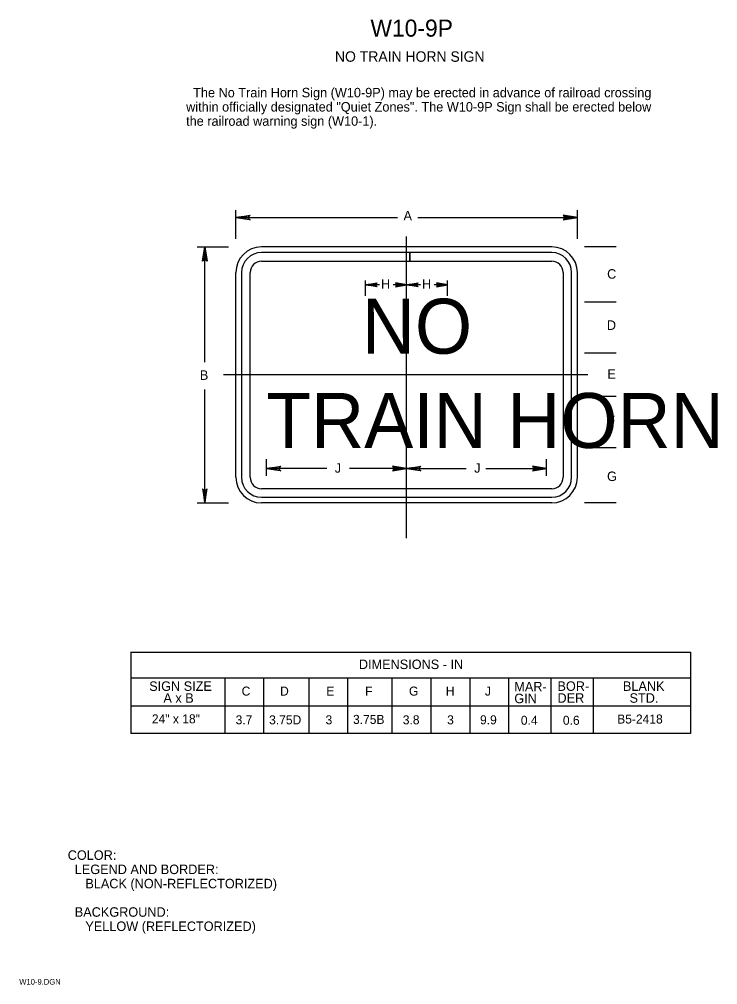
# Model space of a CAD drawing. Extents: x 0.012 to 0.196, y 0.005 to 0.259.
import ezdxf

# ---------------------------------------------------------------- set-up
doc = ezdxf.new("R2010")
doc.units = 0
for name, color, linetype in [('1', 7, 'Continuous'), ('2', 7, 'Continuous'), ('3', 7, 'Continuous')]:
    doc.layers.add(name, color=color, linetype=linetype)

# ---------------------------------------------------------------- blocks, each defined once
blk = doc.blocks.new('RARROW')
at = {"layer": '3'}
for p, q in [((-2.156, 0.285), (-2.2665, 0.384625)), ((-2.2665, 0.384625), (0, 0)), ((0, 0), (-2.2665, -0.379125)), ((-2.156, 0.285), (-2.075625, 0.12075)), ((0, 0), (-2.156, 0.285)), ((-2.14975, -0.2705), (0, 0)), ((-2.075625, 0.12075), (0, 0)), ((0, 0), (-2.074, -0.108)), ((-2.2665, -0.379125), (-2.14975, -0.2705)), ((-2.074, -0.108), (-2.14975, -0.2705))]:
    blk.add_line(p, q, dxfattribs=at)

msp = doc.modelspace()

# ---------------------------------------------------------------- linework, layer by layer
at = {"layer": '1'}
for p, q in [((0.06945, 0.20131), (0.06945, 0.20885)), ((0.15945, 0.20131), (0.15945, 0.20885)), ((0.11445, 0.12237), (0.11445, 0.20194)), ((0.06129, 0.16883), (0.06129, 0.19919)), ((0.11534, 0.19769), (0.0762, 0.19769)), ((0.11534, 0.19769), (0.11534, 0.19544)), ((0.11534, 0.19544), (0.11534, 0.19769)), ((0.1527, 0.19769), (0.11534, 0.19769)), ((0.0762, 0.19544), (0.11534, 0.19544)), ((0.11534, 0.19544), (0.1527, 0.19544)), ((0.07095, 0.19244), (0.07095, 0.13844)), ((0.0732, 0.13844), (0.0732, 0.19244)), ((0.1557, 0.19244), (0.1557, 0.13844)), ((0.15795, 0.13844), (0.15795, 0.19244)), ((0.10365, 0.18625), (0.10365, 0.19033)), ((0.12525, 0.18625), (0.12525, 0.19033)), ((0.16222, 0.16544), (0.06618, 0.16544)), ((0.06129, 0.13169), (0.06129, 0.16162)), ((0.07755, 0.13886), (0.07755, 0.14326)), ((0.15135, 0.13886), (0.15135, 0.14326)), ((0.1527, 0.13544), (0.0762, 0.13544)), ((0.0762, 0.13319), (0.1527, 0.13319))]:
    msp.add_line(p, q, dxfattribs=at)
for centre, radius, start, end in [((0.0762, 0.19244), 0.00675, 90, 180), ((0.1527, 0.19244), 0.00675, 360, 90), ((0.0762, 0.19244), 0.00525, 90, 180), ((0.1527, 0.19244), 0.00525, 0, 90), ((0.0762, 0.19244), 0.003, 90, 180), ((0.1527, 0.19244), 0.003, 0, 90), ((0.0762, 0.13844), 0.00675, 180, 270), ((0.0762, 0.13844), 0.00525, 180, 270), ((0.0762, 0.13844), 0.003, 180, 270), ((0.1527, 0.13844), 0.00675, 270, 0), ((0.1527, 0.13844), 0.003, 270, 0), ((0.1527, 0.13844), 0.00525, 270, 0)]:
    msp.add_arc(centre, radius, start, end, dxfattribs=at)
at = {"layer": '3'}
for p, q in [((0.06945, 0.20692), (0.11208, 0.20692)), ((0.11741, 0.20692), (0.15945, 0.20692)), ((0.05921, 0.19919), (0.06754, 0.19919)), ((0.1527, 0.19919), (0.0762, 0.19919)), ((0.16969, 0.19919), (0.16136, 0.19919)), ((0.06945, 0.13844), (0.06945, 0.19244)), ((0.15945, 0.13844), (0.15945, 0.19244)), ((0.10733, 0.18921), (0.10365, 0.18921)), ((0.11445, 0.18921), (0.11089, 0.18921)), ((0.11813, 0.18921), (0.11445, 0.18921)), ((0.12525, 0.18921), (0.12169, 0.18921)), ((0.16969, 0.18464), (0.16136, 0.18464)), ((0.16969, 0.17114), (0.16136, 0.17114)), ((0.16969, 0.15974), (0.16136, 0.15974)), ((0.16969, 0.14624), (0.16136, 0.14624)), ((0.09341, 0.14075), (0.07755, 0.14075)), ((0.11445, 0.14075), (0.09937, 0.14075)), ((0.11445, 0.14075), (0.13012, 0.14075)), ((0.1353, 0.14075), (0.15135, 0.14075)), ((0.05921, 0.13169), (0.06754, 0.13169)), ((0.1527, 0.13169), (0.0762, 0.13169)), ((0.16969, 0.13169), (0.16136, 0.13169)), ((0.04172, 0.09239), (0.04172, 0.07089)), ((0.04176, 0.09238), (0.18925, 0.09238)), ((0.18925, 0.09238), (0.18925, 0.07088)), ((0.18925, 0.08551), (0.04172, 0.08551)), ((0.06651, 0.08551), (0.06651, 0.07089)), ((0.07672, 0.08551), (0.07672, 0.07089)), ((0.08865, 0.08551), (0.08865, 0.07089)), ((0.0989, 0.08551), (0.0989, 0.07089)), ((0.11058, 0.08551), (0.11058, 0.07089)), ((0.12083, 0.08551), (0.12083, 0.07089)), ((0.13108, 0.08551), (0.13108, 0.07089)), ((0.14133, 0.08551), (0.14133, 0.07089)), ((0.1525, 0.08551), (0.1525, 0.07088)), ((0.16362, 0.08551), (0.16362, 0.07088)), ((0.18925, 0.07814), (0.04172, 0.07814)), ((0.18925, 0.07089), (0.04172, 0.07089))]:
    msp.add_line(p, q, dxfattribs=at)

# ---------------------------------------------------------------- block references
for p, xscale, yscale, rotation in [((0.06945, 0.20692), 0.001654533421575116, 0.0016366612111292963, 180), ((0.06129, 0.19919), 0.001654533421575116, 0.0016366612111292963, 89.99999999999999), ((0.10365, 0.18921), 0.001340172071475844, 0.00132569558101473, 180), ((0.11445, 0.18921), 0.001340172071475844, 0.00132569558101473, 180), ((0.07755, 0.14075), 0.001654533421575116, 0.0016366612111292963, 180), ((0.11445, 0.14075), 0.001654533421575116, 0.0016366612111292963, 180), ((0.06129, 0.13169), 0.001654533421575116, -0.0016366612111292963, -89.99999999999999)]:
    msp.add_blockref('RARROW', p, dxfattribs=dict(at, xscale=xscale, yscale=yscale, rotation=rotation))
for p, xscale, yscale in [((0.15945, 0.20692), 0.001654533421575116, -0.0016366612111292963), ((0.11453, 0.18921), 0.001340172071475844, -0.00132569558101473), ((0.12533, 0.18921), 0.001340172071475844, -0.00132569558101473), ((0.11445, 0.14075), 0.001654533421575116, -0.0016366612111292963), ((0.15135, 0.14075), 0.001654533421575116, -0.0016366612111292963)]:
    msp.add_blockref('RARROW', p, dxfattribs=dict(at, xscale=xscale, yscale=yscale))

# ---------------------------------------------------------------- texts
at = {"layer": '1'}
for s, height, p in [('W10-9P', 0.0045, (0.10492, 0.25462)), ('NO TRAIN HORN SIGN', 0.0027503, (0.09556, 0.248)), ('TRAIN HORN', 0.014492, (0.07744, 0.14618)), ('COLOR:', 0.0025, (0.02513, 0.03759)), ('  LEGEND AND BORDER:', 0.0024998, (0.02513, 0.03384)), ('     BLACK (NON-REFLECTORIZED) ', 0.0024998, (0.02513, 0.03009)), ('  BACKGROUND:', 0.0024998, (0.02513, 0.02259)), ('     YELLOW (REFLECTORIZED)          ', 0.0024998, (0.02513, 0.01884)), ('W10-9.DGN', 0.0015, (0.01236, 0.0047))]:
    msp.add_text(s, height=height, dxfattribs=at).set_placement(p)
msp.add_text('NO', height=0.014492, rotation=360, dxfattribs=at).set_placement((0.10265, 0.17103))
at = {"layer": '2'}
for s, p in [('  The No Train Horn Sign (W10-9P) may be erected in advance of railroad crossing ', (0.05634, 0.23862)), ('within officially designated "Quiet Zones". The W10-9P Sign shall be erected below', (0.05634, 0.23487)), ('the railroad warning sign (W10-1). ', (0.05634, 0.23112))]:
    msp.add_text(s, height=0.0024998, dxfattribs=at).set_placement(p)
at = {"layer": '3'}
for s, height, p in [('A', 0.0025, (0.11363, 0.20619)), ('C', 0.0025, (0.1673, 0.19081)), ('H', 0.0025, (0.1077, 0.18816)), ('H', 0.0025, (0.1185, 0.18816)), ('B', 0.0025, (0.05995, 0.16413)), ('J', 0.0025, (0.09551, 0.13966)), ('DIMENSIONS - IN', 0.0024998, (0.10187, 0.08789)), ('SIGN SIZE', 0.0025, (0.0466, 0.08214)), ('MAR-', 0.0025, (0.14283, 0.08201)), ('BOR-', 0.0025, (0.15421, 0.08214)), ('BLANK', 0.0025, (0.17146, 0.08214)), ('A x B', 0.0025, (0.05035, 0.07901)), ('C', 0.00238, (0.07097, 0.08089)), ('D', 0.00238, (0.0811, 0.08089)), ('E', 0.00238, (0.09327, 0.08089)), ('F', 0.00238, (0.10352, 0.08089)), ('G', 0.00238, (0.11508, 0.08089)), ('J', 0.00238, (0.13509, 0.08089)), ('DER', 0.0025, (0.15421, 0.07901)), ('STD.', 0.0025, (0.17321, 0.07901)), ('GIN', 0.0025, (0.14283, 0.07889)), ('24" x 18"', 0.002375, (0.04731, 0.07357)), ('3.7', 0.002375, (0.06938, 0.07332)), ('3.75D', 0.002375, (0.07821, 0.07332)), ('3', 0.00238, (0.09308, 0.07332)), ('3.75B', 0.002375, (0.10032, 0.07343)), ('3.8', 0.002375, (0.11344, 0.07332)), ('9.9', 0.002375, (0.1338, 0.07332)), ('0.4', 0.002375, (0.14456, 0.0732)), ('B5-2418', 0.002375, (0.16995, 0.07353))]:
    msp.add_text(s, height=height, dxfattribs=at).set_placement(p)
for s, height, p in [('D', 0.0025, (0.16723, 0.17731)), ('E', 0.0025, (0.16737, 0.16445)), ('F', 0.0025, (0.1674, 0.1522)), ('J', 0.0025, (0.13227, 0.13966)), ('G', 0.0025, (0.16728, 0.13746)), ('H', 0.00238, (0.12478, 0.08089)), ('3', 0.00238, (0.12513, 0.07332)), ('0.6', 0.002375, (0.15564, 0.0732))]:
    msp.add_text(s, height=height, rotation=360, dxfattribs=at).set_placement(p)

doc.saveas('drawing.dxf')
